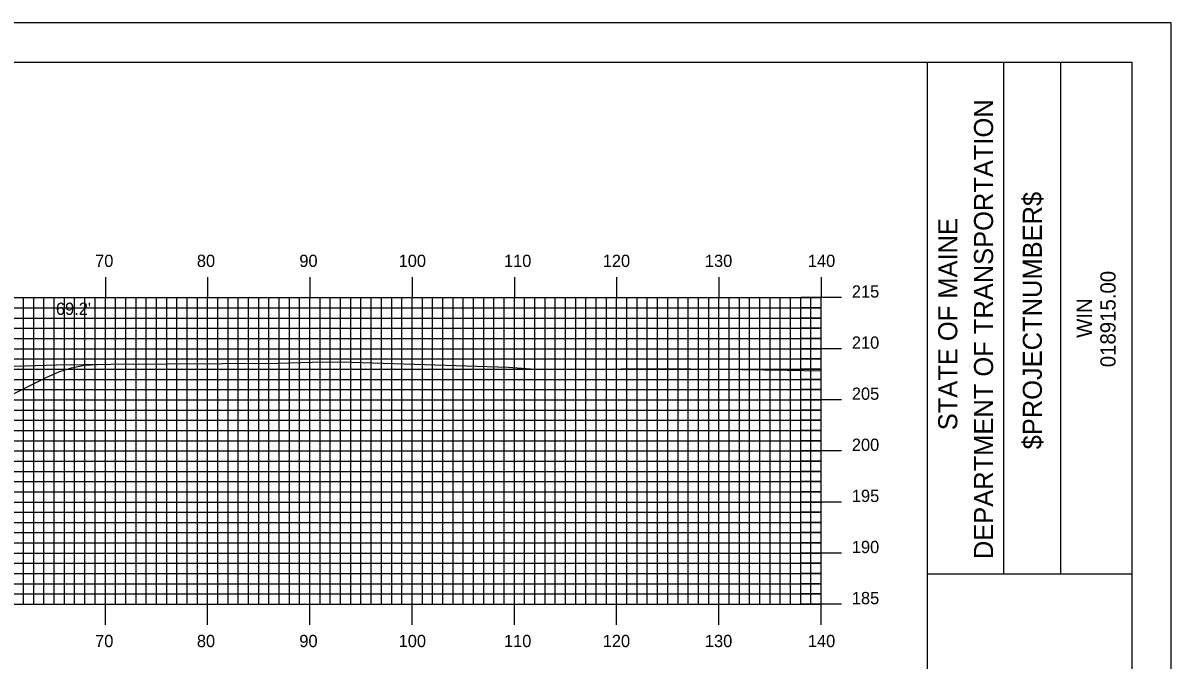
# Model space of a CAD drawing. Extents: x 1799568 to 1799912, y 442591 to 442811.
# Drawn here: x 1799796 to 1799908.2, y 442748.2 to 442810.5 of the extents above; entities that cross this region are included whole.
import ezdxf

# ---------------------------------------------------------------- set-up
doc = ezdxf.new("R2010")
doc.units = 0
for name, color, linetype in [('BORDER', 7, 'Continuous'), ('D_Roadway_Centerline', 7, 'Continuous'), ('D_Roadway_SlopeLines', 7, 'Continuous'), ('D_Text_Standard', 7, 'Continuous'), ('H_V ANNOTATION', 7, 'Continuous'), ('MAJOR', 7, 'Continuous'), ('MINOR', 7, 'Continuous'), ('PLOT BOUNDARY', 7, 'Continuous'), ('S_Roadway_Centerline', 7, 'Continuous')]:
    doc.layers.add(name, color=color, linetype=linetype)

msp = doc.modelspace()

# ---------------------------------------------------------------- linework, layer by layer
at = {"layer": 'BORDER'}
for p, q in [((1799884.41, 442596.67), (1799884.41, 442806.67)), ((1799891.87, 442756.66), (1799891.87, 442806.66)), ((1799897.46, 442756.66), (1799897.46, 442806.66)), ((1799884.41, 442756.65), (1799904.41, 442756.65))]:
    msp.add_line(p, q, dxfattribs=at)
msp.add_lwpolyline([(1799584.41, 442596.67), (1799904.41, 442596.67), (1799904.41, 442806.67), (1799584.41, 442806.67)], close=True, dxfattribs=at)
at = {"layer": 'D_Roadway_Centerline'}
msp.add_lwpolyline([(1799669.45, 442775.1), (1799670.7, 442775.09), (1799671.95, 442774.91), (1799673.2, 442774.55), (1799674.45, 442774.02), (1799699.84, 442761.33), (1799703.84, 442762.33), (1799714.01, 442764.87), (1799722.01, 442765.19), (1799734.01, 442764.95), (1799746.01, 442764.71), (1799754.01, 442764.39), (1799764.18, 442761.85), (1799768.18, 442760.85), (1799798.21, 442775.86), (1799799.46, 442776.41), (1799800.71, 442776.8), (1799801.96, 442777.05), (1799803.21, 442777.14)], dxfattribs=at)
at = {"layer": 'D_Roadway_SlopeLines'}
msp.add_lwpolyline([(1799768.18, 442760.85), (1799798.21, 442775.86), (1799799.46, 442776.41), (1799800.71, 442776.8), (1799801.96, 442777.05), (1799803.21, 442777.14)], dxfattribs=at)
at = {"layer": 'MAJOR'}
for p, q in [((1799804.01, 442785.67), (1799804.01, 442783.67)), ((1799814.01, 442785.67), (1799814.01, 442783.67)), ((1799824.01, 442785.67), (1799824.01, 442783.67)), ((1799834.01, 442785.67), (1799834.01, 442783.67)), ((1799844.01, 442785.67), (1799844.01, 442783.67)), ((1799854.01, 442785.67), (1799854.01, 442783.67)), ((1799864.01, 442785.67), (1799864.01, 442783.67)), ((1799874.01, 442785.67), (1799874.01, 442783.67)), ((1799594.01, 442783.67), (1799874.01, 442783.67)), ((1799594.01, 442783.67), (1799874.01, 442783.67)), ((1799804.01, 442753.67), (1799804.01, 442783.67)), ((1799814.01, 442753.67), (1799814.01, 442783.67)), ((1799824.01, 442753.67), (1799824.01, 442783.67)), ((1799834.01, 442753.67), (1799834.01, 442783.67)), ((1799844.01, 442753.67), (1799844.01, 442783.67)), ((1799854.01, 442753.67), (1799854.01, 442783.67)), ((1799864.01, 442753.67), (1799864.01, 442783.67)), ((1799876.01, 442783.67), (1799872.01, 442783.67)), ((1799874.01, 442753.67), (1799874.01, 442783.67)), ((1799874.01, 442753.67), (1799874.01, 442783.67)), ((1799594.01, 442778.67), (1799874.01, 442778.67)), ((1799876.01, 442778.67), (1799872.01, 442778.67)), ((1799594.01, 442773.67), (1799874.01, 442773.67)), ((1799876.01, 442773.67), (1799872.01, 442773.67)), ((1799594.01, 442768.67), (1799874.01, 442768.67)), ((1799876.01, 442768.67), (1799872.01, 442768.67)), ((1799594.01, 442763.67), (1799874.01, 442763.67)), ((1799876.01, 442763.67), (1799872.01, 442763.67)), ((1799594.01, 442758.67), (1799874.01, 442758.67)), ((1799876.01, 442758.67), (1799872.01, 442758.67)), ((1799594.01, 442753.67), (1799874.01, 442753.67)), ((1799594.01, 442753.67), (1799874.01, 442753.67)), ((1799804.01, 442751.66), (1799804.01, 442753.67)), ((1799814.01, 442751.66), (1799814.01, 442753.67)), ((1799824.01, 442751.66), (1799824.01, 442753.67)), ((1799834.01, 442751.66), (1799834.01, 442753.67)), ((1799844.01, 442751.66), (1799844.01, 442753.67)), ((1799854.01, 442751.66), (1799854.01, 442753.67)), ((1799864.01, 442751.66), (1799864.01, 442753.67)), ((1799876.01, 442753.67), (1799872.01, 442753.67)), ((1799874.01, 442751.66), (1799874.01, 442753.67))]:
    msp.add_line(p, q, dxfattribs=at)
at = {"layer": 'MINOR'}
for p, q in [((1799796.01, 442753.67), (1799796.01, 442783.67)), ((1799797.01, 442753.67), (1799797.01, 442783.67)), ((1799798.01, 442753.67), (1799798.01, 442783.67)), ((1799799.01, 442753.67), (1799799.01, 442783.67)), ((1799800.01, 442753.67), (1799800.01, 442783.67)), ((1799801.01, 442753.67), (1799801.01, 442783.67)), ((1799802.01, 442753.67), (1799802.01, 442783.67)), ((1799803.01, 442753.67), (1799803.01, 442783.67)), ((1799805.01, 442753.67), (1799805.01, 442783.67)), ((1799806.01, 442753.67), (1799806.01, 442783.67)), ((1799807.01, 442753.67), (1799807.01, 442783.67)), ((1799808.01, 442753.67), (1799808.01, 442783.67)), ((1799809.01, 442753.67), (1799809.01, 442783.67)), ((1799810.01, 442753.67), (1799810.01, 442783.67)), ((1799811.01, 442753.67), (1799811.01, 442783.67)), ((1799812.01, 442753.67), (1799812.01, 442783.67)), ((1799813.01, 442753.67), (1799813.01, 442783.67)), ((1799815.01, 442753.67), (1799815.01, 442783.67)), ((1799816.01, 442753.67), (1799816.01, 442783.67)), ((1799817.01, 442753.67), (1799817.01, 442783.67)), ((1799818.01, 442753.67), (1799818.01, 442783.67)), ((1799819.01, 442753.67), (1799819.01, 442783.67)), ((1799820.01, 442753.67), (1799820.01, 442783.67)), ((1799821.01, 442753.67), (1799821.01, 442783.67)), ((1799822.01, 442753.67), (1799822.01, 442783.67)), ((1799823.01, 442753.67), (1799823.01, 442783.67)), ((1799825.01, 442753.67), (1799825.01, 442783.67)), ((1799826.01, 442753.67), (1799826.01, 442783.67)), ((1799827.01, 442753.67), (1799827.01, 442783.67)), ((1799828.01, 442753.67), (1799828.01, 442783.67)), ((1799829.01, 442753.67), (1799829.01, 442783.67)), ((1799830.01, 442753.67), (1799830.01, 442783.67)), ((1799831.01, 442753.67), (1799831.01, 442783.67)), ((1799832.01, 442753.67), (1799832.01, 442783.67)), ((1799833.01, 442753.67), (1799833.01, 442783.67)), ((1799835.01, 442753.67), (1799835.01, 442783.67)), ((1799836.01, 442753.67), (1799836.01, 442783.67)), ((1799837.01, 442753.67), (1799837.01, 442783.67)), ((1799838.01, 442753.67), (1799838.01, 442783.67)), ((1799839.01, 442753.67), (1799839.01, 442783.67)), ((1799840.01, 442753.67), (1799840.01, 442783.67)), ((1799841.01, 442753.67), (1799841.01, 442783.67)), ((1799842.01, 442753.67), (1799842.01, 442783.67)), ((1799843.01, 442753.67), (1799843.01, 442783.67)), ((1799845.01, 442753.67), (1799845.01, 442783.67)), ((1799846.01, 442753.67), (1799846.01, 442783.67)), ((1799847.01, 442753.67), (1799847.01, 442783.67)), ((1799848.01, 442753.67), (1799848.01, 442783.67)), ((1799849.01, 442753.67), (1799849.01, 442783.67)), ((1799850.01, 442753.67), (1799850.01, 442783.67)), ((1799851.01, 442753.67), (1799851.01, 442783.67)), ((1799852.01, 442753.67), (1799852.01, 442783.67)), ((1799853.01, 442753.67), (1799853.01, 442783.67)), ((1799855.01, 442753.67), (1799855.01, 442783.67)), ((1799856.01, 442753.67), (1799856.01, 442783.67)), ((1799857.01, 442753.67), (1799857.01, 442783.67)), ((1799858.01, 442753.67), (1799858.01, 442783.67)), ((1799859.01, 442753.67), (1799859.01, 442783.67)), ((1799860.01, 442753.67), (1799860.01, 442783.67)), ((1799861.01, 442753.67), (1799861.01, 442783.67)), ((1799862.01, 442753.67), (1799862.01, 442783.67)), ((1799863.01, 442753.67), (1799863.01, 442783.67)), ((1799865.01, 442753.67), (1799865.01, 442783.67)), ((1799866.01, 442753.67), (1799866.01, 442783.67)), ((1799867.01, 442753.67), (1799867.01, 442783.67)), ((1799868.01, 442753.67), (1799868.01, 442783.67)), ((1799869.01, 442753.67), (1799869.01, 442783.67)), ((1799870.01, 442753.67), (1799870.01, 442783.67)), ((1799871.01, 442753.67), (1799871.01, 442783.67)), ((1799872.01, 442753.67), (1799872.01, 442783.67)), ((1799873.01, 442753.67), (1799873.01, 442783.67)), ((1799594.01, 442782.67), (1799874.01, 442782.67)), ((1799874.01, 442782.67), (1799872.01, 442782.67)), ((1799594.01, 442781.67), (1799874.01, 442781.67)), ((1799874.01, 442781.67), (1799872.01, 442781.67)), ((1799594.01, 442780.67), (1799874.01, 442780.67)), ((1799874.01, 442780.67), (1799872.01, 442780.67)), ((1799594.01, 442779.67), (1799874.01, 442779.67)), ((1799874.01, 442779.67), (1799872.01, 442779.67)), ((1799594.01, 442777.67), (1799874.01, 442777.67)), ((1799874.01, 442777.67), (1799872.01, 442777.67)), ((1799594.01, 442776.67), (1799874.01, 442776.67)), ((1799874.01, 442776.67), (1799872.01, 442776.67)), ((1799594.01, 442775.67), (1799874.01, 442775.67)), ((1799594.01, 442774.67), (1799874.01, 442774.67)), ((1799874.01, 442775.67), (1799872.01, 442775.67)), ((1799874.01, 442774.67), (1799872.01, 442774.67)), ((1799594.01, 442772.67), (1799874.01, 442772.67)), ((1799874.01, 442772.67), (1799872.01, 442772.67)), ((1799594.01, 442771.67), (1799874.01, 442771.67)), ((1799874.01, 442771.67), (1799872.01, 442771.67)), ((1799594.01, 442770.67), (1799874.01, 442770.67)), ((1799874.01, 442770.67), (1799872.01, 442770.67)), ((1799594.01, 442769.67), (1799874.01, 442769.67)), ((1799874.01, 442769.67), (1799872.01, 442769.67)), ((1799594.01, 442767.67), (1799874.01, 442767.67)), ((1799874.01, 442767.67), (1799872.01, 442767.67)), ((1799594.01, 442766.67), (1799874.01, 442766.67)), ((1799594.01, 442765.67), (1799874.01, 442765.67)), ((1799874.01, 442766.67), (1799872.01, 442766.67)), ((1799874.01, 442765.67), (1799872.01, 442765.67)), ((1799594.01, 442764.67), (1799874.01, 442764.67)), ((1799874.01, 442764.67), (1799872.01, 442764.67)), ((1799594.01, 442762.67), (1799874.01, 442762.67)), ((1799874.01, 442762.67), (1799872.01, 442762.67)), ((1799594.01, 442761.67), (1799874.01, 442761.67)), ((1799874.01, 442761.67), (1799872.01, 442761.67)), ((1799594.01, 442760.67), (1799874.01, 442760.67)), ((1799874.01, 442760.67), (1799872.01, 442760.67)), ((1799594.01, 442759.67), (1799874.01, 442759.67)), ((1799874.01, 442759.67), (1799872.01, 442759.67)), ((1799594.01, 442757.67), (1799874.01, 442757.67)), ((1799594.01, 442756.67), (1799874.01, 442756.67)), ((1799874.01, 442757.67), (1799872.01, 442757.67)), ((1799874.01, 442756.67), (1799872.01, 442756.67)), ((1799594.01, 442755.67), (1799874.01, 442755.67)), ((1799874.01, 442755.67), (1799872.01, 442755.67)), ((1799594.01, 442754.67), (1799874.01, 442754.67)), ((1799874.01, 442754.67), (1799872.01, 442754.67))]:
    msp.add_line(p, q, dxfattribs=at)
at = {"layer": 'PLOT BOUNDARY'}
msp.add_lwpolyline([(1799568.22, 442590.55), (1799908.22, 442590.55), (1799908.22, 442810.55), (1799568.22, 442810.55)], close=True, dxfattribs=at)
at = {"layer": 'S_Roadway_Centerline'}
msp.add_lwpolyline([(1799788.87, 442776.77), (1799799.24, 442777.09), (1799804.54, 442777.16), (1799820.9, 442777.25), (1799824.22, 442777.35), (1799827.11, 442777.39), (1799843.39, 442776.87), (1799846.49, 442776.62), (1799850.15, 442776.67), (1799858.76, 442776.72), (1799866.21, 442776.63), (1799870.67, 442776.56), (1799874.01, 442776.51)], dxfattribs=at)

# ---------------------------------------------------------------- texts
at = {"layer": 'BORDER'}
for s, height, p in [('DEPARTMENT OF TRANSPORTATION', 1.8635, (1799890.82, 442758.08)), ('$PROJECTNUMBER$', 1.8635, (1799895.59, 442768.82)), ('STATE OF MAINE', 1.8635, (1799887.32, 442770.69)), ('018915.00', 1.491, (1799902.8, 442776.86)), ('WIN', 1.491, (1799900.48, 442779.73))]:
    msp.add_text(s, height=height, rotation=90, dxfattribs=at).set_placement(p)
at = {"layer": 'D_Text_Standard'}
msp.add_text("69.2'", height=1.2, dxfattribs=at).set_placement((1799799.18, 442781.98))
at = {"layer": 'H_V ANNOTATION'}
for s, p in [('70', (1799803.01, 442786.67)), ('80', (1799812.96, 442786.67)), ('90', (1799822.98, 442786.67)), ('100', (1799832.69, 442786.67)), ('110', (1799842.99, 442786.67)), ('120', (1799852.65, 442786.67)), ('130', (1799862.64, 442786.67)), ('140', (1799872.71, 442786.67)), ('215', (1799877.01, 442783.67)), ('210', (1799877.01, 442778.67)), ('205', (1799877.01, 442773.67)), ('200', (1799877.01, 442768.67)), ('195', (1799877.01, 442763.67)), ('190', (1799877.01, 442758.67)), ('185', (1799877.01, 442753.67)), ('70', (1799803.01, 442749.47)), ('80', (1799812.96, 442749.47)), ('90', (1799822.98, 442749.47)), ('100', (1799832.69, 442749.47)), ('110', (1799842.99, 442749.47)), ('120', (1799852.65, 442749.47)), ('130', (1799862.64, 442749.47)), ('140', (1799872.71, 442749.47))]:
    msp.add_text(s, height=1.2, dxfattribs=at).set_placement(p)

doc.saveas('drawing.dxf')
